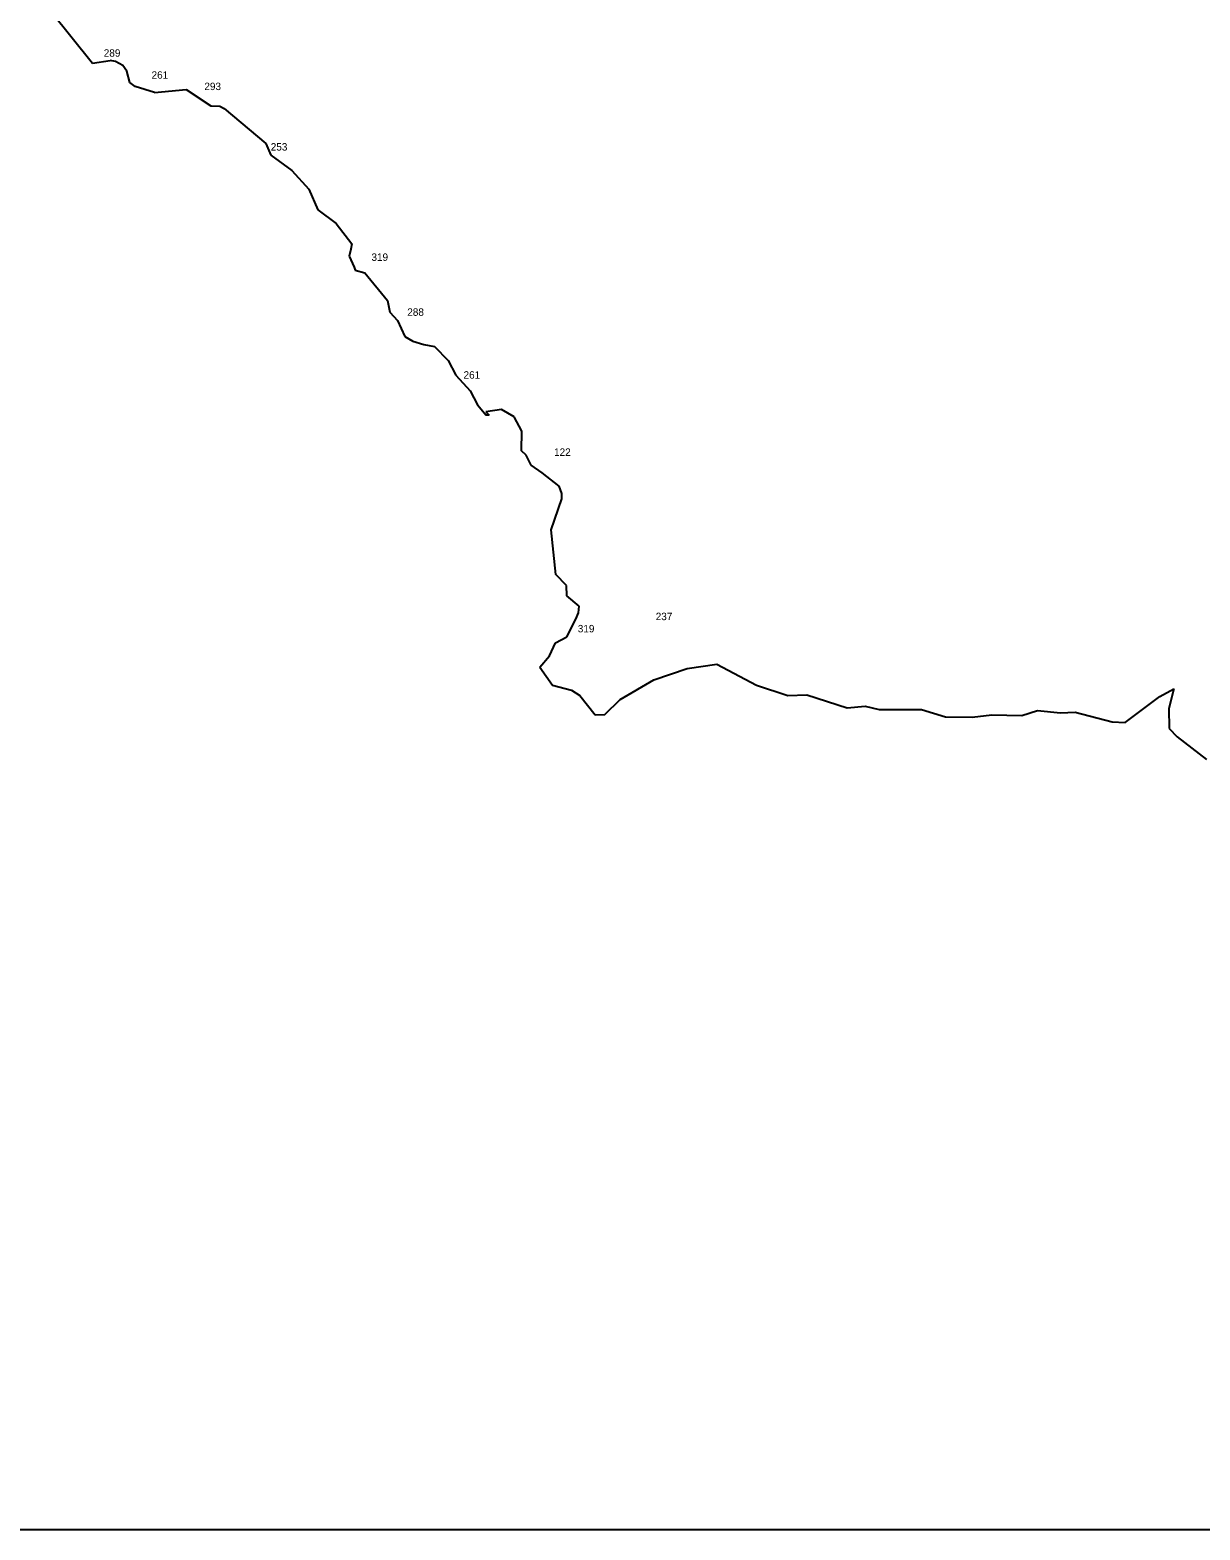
# Model space of a CAD drawing. Extents: x -780246 to -774760, y -968897 to -964868.
# Drawn here: x -779076 to -777505, y -968897 to -966883 of the extents above; entities that cross this region are included whole.
import ezdxf

# ---------------------------------------------------------------- set-up
doc = ezdxf.new("R2010")
doc.units = 0
doc.layers.add('Vrstva 13', color=7, linetype='Continuous')
doc.layers.add('Vrstva 15', color=7, linetype='Continuous')

msp = doc.modelspace()

# ---------------------------------------------------------------- linework, layer by layer
at = {"layer": 'Vrstva 13'}
for p, q in [((-779048.33, -966857.77), (-778991.94, -966927.92)), ((-778991.94, -966927.92), (-778968.06, -966924.48)), ((-778960.83, -966925.58), (-778968.06, -966924.48)), ((-778951.06, -966931.24), (-778960.83, -966925.58)), ((-778945.93, -966938.59), (-778951.06, -966931.24)), ((-778941.54, -966953.78), (-778945.93, -966938.59)), ((-778934.53, -966959.34), (-778941.54, -966953.78)), ((-778908.82, -966967.38), (-778934.53, -966959.34)), ((-778908.82, -966967.38), (-778866.02, -966963.57)), ((-778866.02, -966963.57), (-778833.07, -966985.12)), ((-778833.07, -966985.12), (-778820.72, -966985.93)), ((-778820.72, -966985.93), (-778815.02, -966988.86)), ((-778815.02, -966988.86), (-778758.93, -967036.06)), ((-778758.93, -967036.06), (-778752.5, -967051.69)), ((-778752.5, -967051.69), (-778724.15, -967072.01)), ((-778724.15, -967072.01), (-778701.22, -967097.28)), ((-778701.22, -967097.28), (-778689.1, -967125.05)), ((-778689.1, -967125.05), (-778664.56, -967143.32)), ((-778664.56, -967143.32), (-778643.73, -967170.35)), ((-778644.83, -967177.66), (-778647.46, -967186.87)), ((-778643.73, -967170.35), (-778644.83, -967177.66)), ((-778647.46, -967186.87), (-778640.52, -967201.71)), ((-778640.52, -967201.71), (-778639.29, -967205.87)), ((-778639.29, -967205.87), (-778626.21, -967209.6)), ((-778626.21, -967209.6), (-778595.68, -967246.79)), ((-778595.68, -967246.79), (-778592.57, -967262.17)), ((-778592.57, -967262.17), (-778582.24, -967273.46)), ((-778582.24, -967273.46), (-778572.34, -967295.06)), ((-778572.34, -967295.06), (-778561.56, -967301.09)), ((-778561.56, -967301.09), (-778546.81, -967305.84)), ((-778546.81, -967305.84), (-778532.86, -967308.47)), ((-778532.86, -967308.47), (-778514.38, -967326.96)), ((-778514.38, -967326.96), (-778504, -967346.68)), ((-778504, -967346.68), (-778485.02, -967367.88)), ((-778485.02, -967367.88), (-778475.16, -967386.59)), ((-778475.16, -967386.59), (-778463.25, -967400.47)), ((-778442.94, -967392.86), (-778463.83, -967396.08)), ((-778463.83, -967396.08), (-778459.45, -967400.61)), ((-778459.45, -967400.61), (-778463.25, -967400.47)), ((-778425.7, -967402.66), (-778442.94, -967392.86)), ((-778415.33, -967421.8), (-778425.7, -967402.66)), ((-778415.92, -967448.4), (-778415.33, -967421.8)), ((-778409.5, -967454.03), (-778415.92, -967448.4)), ((-778402.71, -967467.54), (-778409.5, -967454.03)), ((-778388.18, -967478.07), (-778402.71, -967467.54)), ((-778365.53, -967495.83), (-778388.18, -967478.07)), ((-778361.66, -967505.76), (-778365.53, -967495.83)), ((-778361.59, -967512.92), (-778361.66, -967505.76)), ((-778376.05, -967554.49), (-778361.59, -967512.92)), ((-778369.77, -967614.19), (-778376.05, -967554.49)), ((-778355.6, -967629.24), (-778369.77, -967614.19)), ((-778355.02, -967642.84), (-778355.6, -967629.24)), ((-778338.36, -967657.01), (-778355.02, -967642.84)), ((-778342.75, -967674.25), (-778339.39, -967665.92)), ((-778339.39, -967665.92), (-778338.36, -967657.01)), ((-778355.16, -967698.22), (-778342.75, -967674.25)), ((-778378.53, -967723.65), (-778370.35, -967706.26)), ((-778370.35, -967706.26), (-778355.16, -967698.22)), ((-778391.24, -967738.7), (-778378.53, -967723.65)), ((-778391.24, -967738.7), (-778374.45, -967763.07)), ((-778238.21, -967755.84), (-778193.51, -967740.79)), ((-778193.51, -967740.79), (-778153.62, -967734.65)), ((-778153.62, -967734.65), (-778100.59, -967762.86)), ((-778374.45, -967763.07), (-778348.59, -967769.79)), ((-778348.59, -967769.79), (-778337.45, -967776.73)), ((-778283.42, -967782.36), (-778238.21, -967755.84)), ((-778100.59, -967762.86), (-778058.52, -967776.74)), ((-777558.78, -967778.05), (-777540.08, -967767.74)), ((-777540.08, -967767.74), (-777546.87, -967794.49)), ((-778337.45, -967776.73), (-778316.81, -967802.75)), ((-778304.03, -967802.16), (-778283.42, -967782.36)), ((-778058.52, -967776.74), (-778032.65, -967776.08)), ((-778032.65, -967776.08), (-777978.59, -967793.4)), ((-777605.38, -967812.89), (-777558.78, -967778.05)), ((-778316.81, -967802.75), (-778304.03, -967802.16)), ((-777978.59, -967793.4), (-777954.41, -967791.28)), ((-777954.41, -967791.28), (-777935.86, -967795.52)), ((-777935.86, -967795.52), (-777878.95, -967795.74)), ((-777878.95, -967795.74), (-777846.88, -967805.67)), ((-777846.88, -967805.67), (-777810.72, -967805.89)), ((-777810.72, -967805.89), (-777784.64, -967802.6)), ((-777784.64, -967802.6), (-777744.25, -967803.62)), ((-777744.25, -967803.62), (-777722.99, -967796.97)), ((-777722.99, -967796.97), (-777692.45, -967800.11)), ((-777692.45, -967800.11), (-777672.81, -967799.23)), ((-777672.81, -967799.23), (-777622.91, -967812.09)), ((-777546.87, -967794.49), (-777546.43, -967821.23)), ((-777622.91, -967812.09), (-777605.38, -967812.89)), ((-777546.43, -967821.23), (-777535.83, -967832.2)), ((-777535.83, -967832.2), (-777496.1, -967862.6))]:
    msp.add_line(p, q, dxfattribs=at)
msp.add_lwpolyline([(-780246.31, -964867.52), (-774759.73, -964867.52), (-774759.73, -968897.03), (-780246.31, -968897.03)], close=True, dxfattribs=at)

# ---------------------------------------------------------------- texts
at = {"layer": 'Vrstva 15'}
for s, p in [('289', (-778976.71, -966919.35)), ('261', (-778912.524, -966948.91)), ('293', (-778841.62, -966964.13)), ('253', (-778752.516, -967045.35)), ('319', (-778617.324, -967193.41)), ('288', (-778569.236, -967267.14)), ('261', (-778493.694, -967351.53)), ('122', (-778372.151, -967455.12)), ('237', (-778235.686, -967675.68)), ('319', (-778340.324, -967692.07))]:
    msp.add_text(s, height=10, dxfattribs=at).set_placement(p)

doc.saveas('drawing.dxf')
